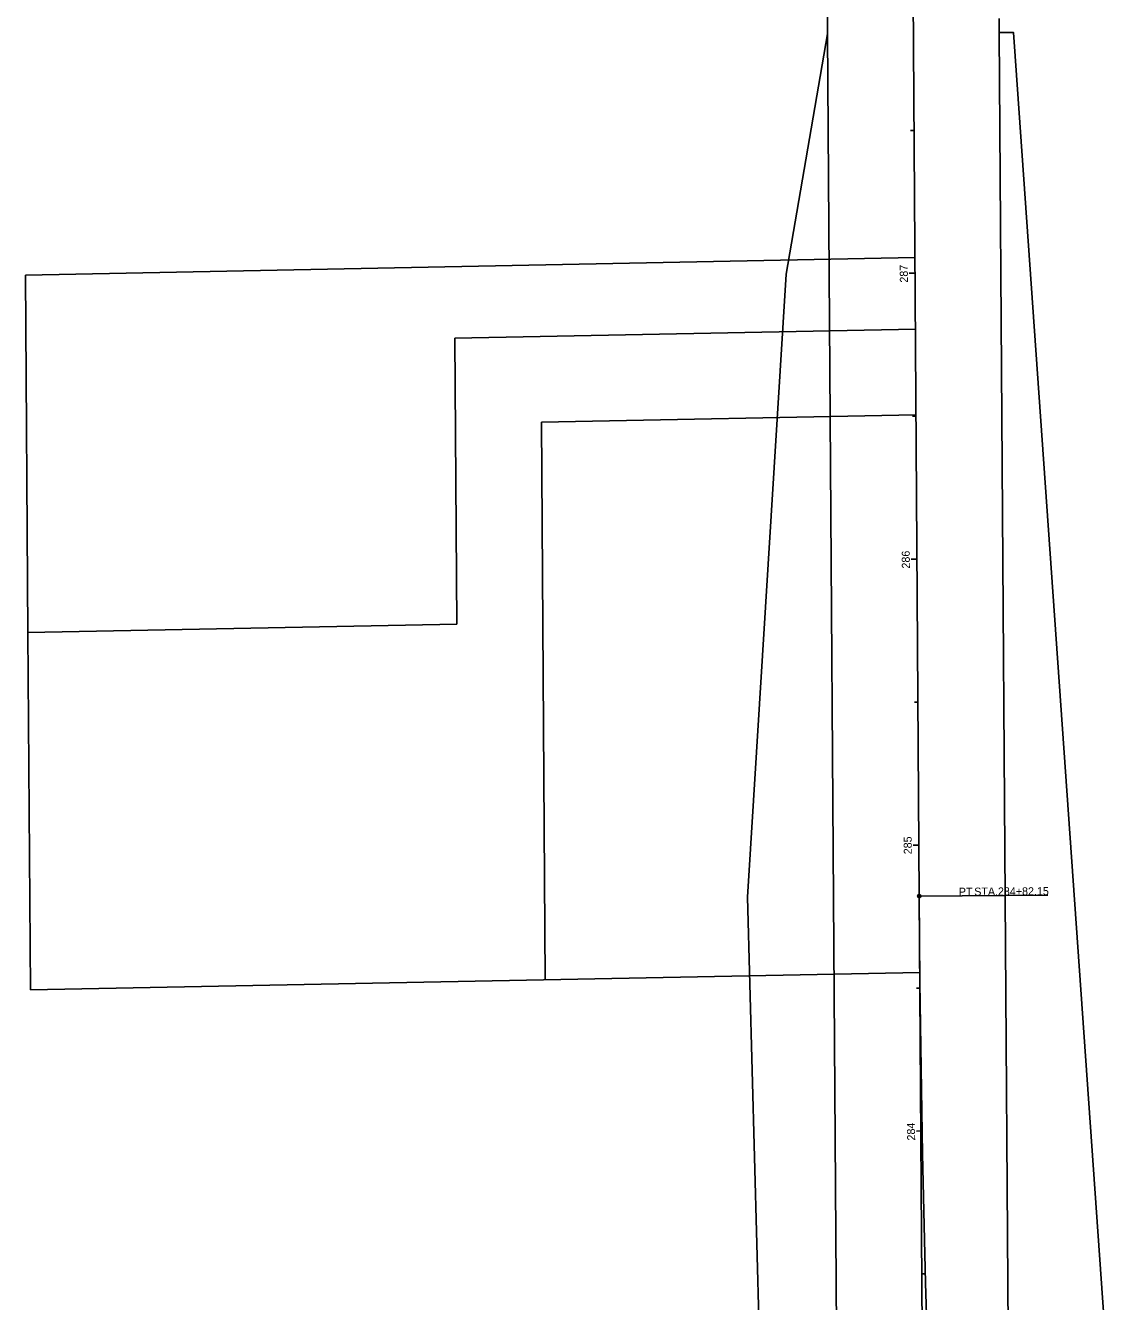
# Model space of a CAD drawing. Extents: x 1721910 to 1725197, y 328771 to 332519.
# Drawn here: x 1722604.4 to 1722987.9, y 331267 to 331713.3 of the extents above; entities that cross this region are included whole.
import ezdxf

# ---------------------------------------------------------------- set-up
doc = ezdxf.new("R2010")
doc.units = 0
for name, color, linetype in [('BR_P_Gen_Approach_Slab', 7, 'Continuous'), ('DT_P_Graded_Shoulder', 7, 'Continuous'), ('PV_P_EOP', 7, 'Continuous'), ('RW_P_Const_Limits', 7, 'Continuous'), ('SC_Scratch1', 7, 'Continuous')]:
    doc.layers.add(name, color=color, linetype=linetype)

msp = doc.modelspace()

# ---------------------------------------------------------------- linework, layer by layer
at = {"layer": 'BR_P_Gen_Approach_Slab'}
for p, q in [((1722889.04, 331093.19), (1722884.82, 331710.44)), ((1722949.11, 331083.44), (1722944.82, 331710.85)), ((1722604.42, 331626), (1722915.35, 331632.14)), ((1722605.27, 331501), (1722604.42, 331626)), ((1722754.56, 331603.96), (1722915.53, 331607.14)), ((1722755.24, 331503.96), (1722754.56, 331603.96)), ((1722784.76, 331574.55), (1722915.73, 331577.14)), ((1722786.09, 331379.56), (1722784.76, 331574.55)), ((1722605.27, 331501), (1722755.24, 331503.96)), ((1722606.12, 331376), (1722605.27, 331501)), ((1722916.88, 331408.8), (1722920.17, 330927.13)), ((1722606.12, 331376), (1722917.06, 331382.14))]:
    msp.add_line(p, q, dxfattribs=at)
at = {"layer": 'DT_P_Graded_Shoulder'}
msp.add_line((1722916.88, 331408.8), (1722912.14, 332102.1), dxfattribs=at)
msp.add_arc((1730078.68, 331457.77), 7161.97, 180.391728, 188.087121, dxfattribs=at)
at = {"layer": 'PV_P_EOP'}
for p, q in [((1722884.82, 331710.44), (1722882.14, 332101.89)), ((1722870.39, 331626.34), (1722884.82, 331710.44)), ((1722944.82, 331710.85), (1722949.82, 331710.89)), ((1722856.88, 331408.39), (1722870.39, 331626.34)), ((1722864.43, 331124), (1722856.88, 331408.39))]:
    msp.add_line(p, q, dxfattribs=at)
msp.add_lwpolyline([(1722987.2, 331178.83), (1722949.82, 331710.89), (1722944.82, 331710.85), (1722944.78, 331715.74)], dxfattribs=at)
at = {"layer": 'RW_P_Const_Limits'}
msp.add_line((1722916.88, 331408.8), (1722961.88, 331409.11), dxfattribs=at)
msp.add_circle((1722916.88, 331408.8), 0.6, dxfattribs=at)
at = {"layer": 'SC_Scratch1'}
for p, q in [((1722915.05, 331676.65), (1722913.85, 331676.64)), ((1722915.39, 331626.65), (1722913.39, 331626.64)), ((1722915.73, 331576.65), (1722914.53, 331576.64)), ((1722916.08, 331526.65), (1722914.08, 331526.64)), ((1722916.42, 331476.65), (1722915.22, 331476.64)), ((1722916.76, 331426.65), (1722914.76, 331426.64)), ((1722917.17, 331376.66), (1722915.97, 331376.64)), ((1722917.91, 331326.66), (1722915.91, 331326.62)), ((1722919, 331276.67), (1722917.8, 331276.64))]:
    msp.add_line(p, q, dxfattribs=at)

# ---------------------------------------------------------------- texts
at = {"layer": 'RW_P_Const_Limits'}
for s, p in [('PT', (1722930.73, 331408.93)), (' STA. ', (1722935.08, 331408.96)), ('284+82.15', (1722944.4, 331409.03))]:
    msp.add_text(s, height=2.8, rotation=0.3917, dxfattribs=at).set_placement(p)
at = {"layer": 'SC_Scratch1'}
for s, rotation, p in [('287', 90.3917, (1722912.91, 331623.39)), ('286', 90.3917, (1722913.6, 331523.38)), ('285', 90.3917, (1722914.28, 331423.43)), ('284', 91.0489, (1722915.47, 331323.34))]:
    msp.add_text(s, height=2.8, rotation=rotation, dxfattribs=at).set_placement(p)

doc.saveas('drawing.dxf')
